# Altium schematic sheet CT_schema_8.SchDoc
size 274 x 160 mm
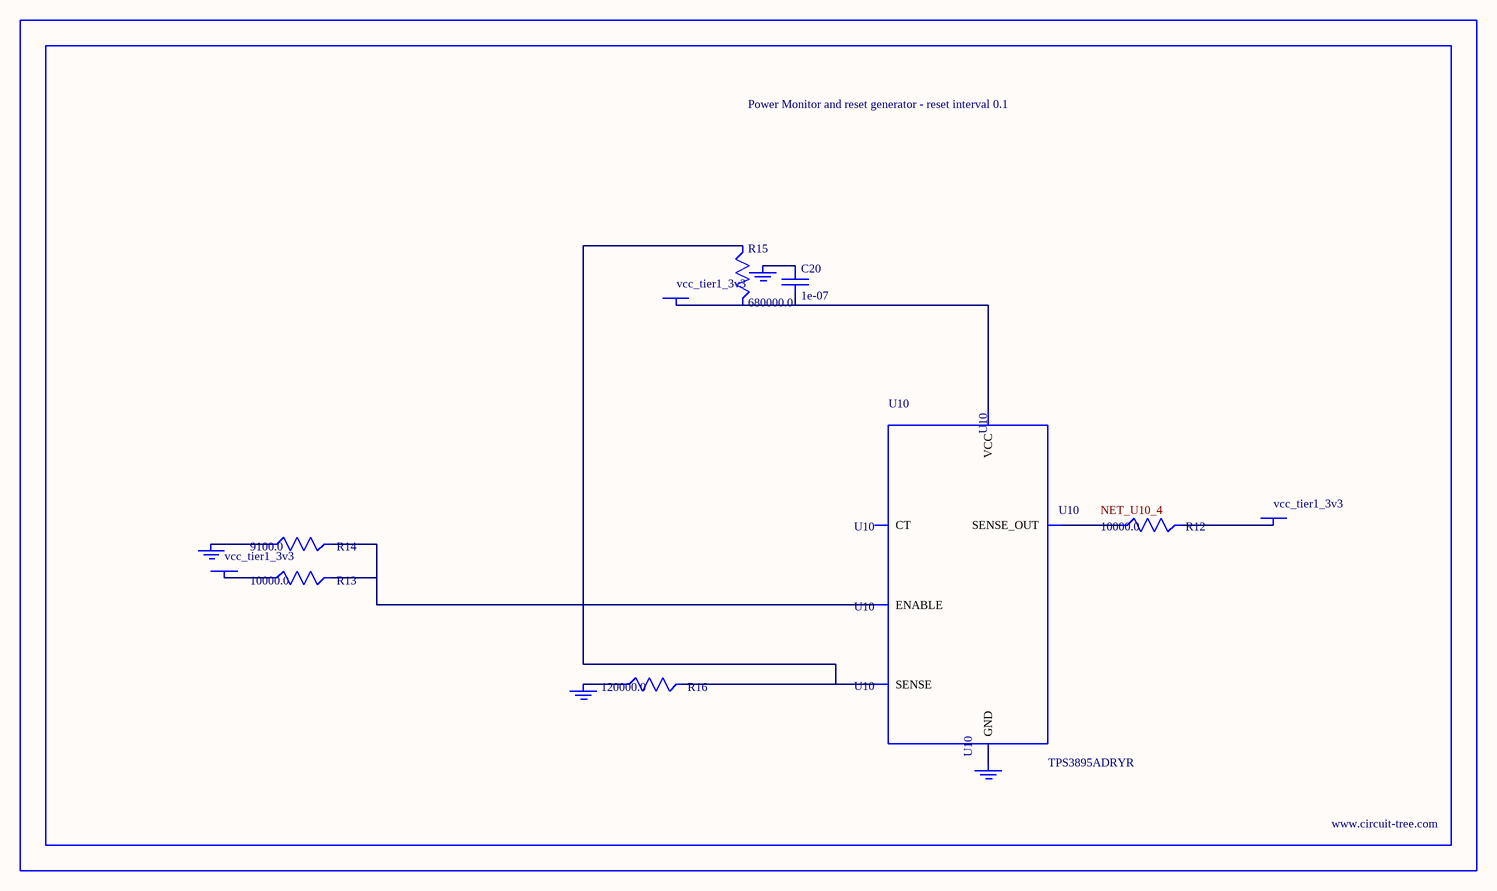
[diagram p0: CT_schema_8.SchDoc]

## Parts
BORDER7  (no value)
C20  1e-07  [C0402]
GND_INSTANCE_7_0  (no value)
GND_INSTANCE_7_1  (no value)
GND_INSTANCE_7_2  (no value)
GND_INSTANCE_7_3  (no value)
POWER_INSTANCE_7_0  vcc_tier1_3v3
POWER_INSTANCE_7_1  vcc_tier1_3v3
POWER_INSTANCE_7_2  vcc_tier1_3v3
R12  10000.0  [R0603]
R13  10000.0  [R0603]
R14  9100.0  [R0603]
R15  680000.0  [R0603]
R16  120000.0  [R0603]
U10  TPS3895ADRYR  [SON-6]

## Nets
NetC20_1: C20.1 GND_INSTANCE_7_2.0(GND)
NetC20_2: C20.2 POWER_INSTANCE_7_2.0(PWR) R15.2 U10.6(VCC)
NetGND_INSTANCE_7_0_0: GND_INSTANCE_7_0.0(GND) R14.1
NetGND_INSTANCE_7_1_0: GND_INSTANCE_7_1.0(GND) R16.1
NetGND_INSTANCE_7_3_0: GND_INSTANCE_7_3.0(GND) U10.2(GND)
NetPOWER_INSTANCE_7_0_0: POWER_INSTANCE_7_0.0(PWR) R13.1
NetPOWER_INSTANCE_7_1_0: POWER_INSTANCE_7_1.0(PWR) R12.2
NetR12_1: R12.1 U10.4(SENSE_OUT)
NetR13_2: R13.2 R14.2 U10.1(ENABLE)
NetR15_1: R15.1 R16.2 U10.3(SENSE)

Not connected (* = marked no-connect by the designer): U10 5(CT)

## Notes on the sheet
- Labels drawn without touching a wire or pin: NET_U10_4

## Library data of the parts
BORDER7 = BORDER_PAGE7
C20 = C0402C104K3RACTU
GND_INSTANCE_7_0-GND_INSTANCE_7_3 = GND
POWER_INSTANCE_7_0-POWER_INSTANCE_7_2 = PWR
R12 R13 = RC0603JR-0710KL
R14 = RC0603JR-079K1L
R15 = RC0603JR-07680KL
R16 = RC0603JR-07120KL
